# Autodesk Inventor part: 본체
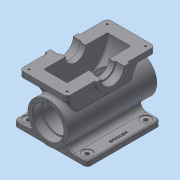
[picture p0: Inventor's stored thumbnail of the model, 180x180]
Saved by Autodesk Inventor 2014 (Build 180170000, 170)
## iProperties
Created: 2023-07
Part Number: 본체
Material: 일반
Document SubType Name: Modeling
Designer: dg
Density: 1 g/cm^3
Appearance: 기본값
Author: dg
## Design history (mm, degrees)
sketch "스케치1"
  geometry: L1 (-121, 0)-(121, 0); L2 (-121, 0)-(-121, 55); L3 (-121, 55)-(121, 55); L4 (121, 55)-(121, 0); L5 (-121, 42.5)-(-96, 42.5); L6 (-96, 42.5)-(-96, 38.5); L7 (-96, 38.5)-(96, 38.5); L8 (96, 38.5)-(96, 42.5); L9 (96, 42.5)-(121, 42.5); 2 further points
  constraints: 18 end point, 5 perpendicular, 3 parallel, 2 coincident, 2 point on line, 1 horizontal, 1 midpoint
  dimensions: "d0" = 242 distance of L1.start L1.end; "d1" = 110 diameter of L3 L1; "d2" = 85 diameter of L5 L1; "d3" = 77 diameter of L7 L1; "d4" = 85 diameter of L9 L1; "d5" = 25 distance between parallel lines of L4 L8; "d6" = 25 distance between parallel lines of L2 L6
revolve "회전1" sketch "스케치1" stored, may be unused: angle "d7" = 90 deg
node "작업 평면1"
sketch "스케치2"
  geometry: L1 (-100, -45)-(100, -45); L2 (100, -45)-(100, -60); L3 (100, -60)-(-100, -60); L4 (-100, -60)-(-100, -45); 2 further points
  constraints: 8 end point, 2 parallel, 1 horizontal, 1 midpoint, 1 perpendicular, 1 vertical alignment
  dimensions: "d9" = 60 distance from line of L3 point (0, 0); "d10" = 15 distance between parallel lines of L3 L1; "d11" = 200 distance between parallel lines of L2 L4
extrude "돌출1" join sketch "스케치2" stored distance "d12" = 200; taper "d13" = 0 deg
fillet "모깎기1" dims "d14" = 15
sketch "스케치3"
  geometry: L1 (-114, -60)-(86, -60) reference; L2 (-121, -55)-(-121, 55) reference; L3 (-114, 100)-(86, 100); L4 (86, -55)-(86, -60) reference; L5 (86, -60)-(-114, -60) reference; L6 (-114, -60)-(-114, -55) reference; L7 (-114, -55)-(-121, -55) reference; L8 (-121, -55)-(-121, -42.5) reference; L9 (-121, -42.5)-(-96, -42.5) reference; L10 (-96, -42.5)-(-96, -38.5) reference; L11 (-96, -38.5)-(96, -38.5) reference; L12 (96, -38.5)-(96, -42.5) reference; L13 (96, -42.5)-(121, -42.5) reference; L14 (121, -42.5)-(121, -55) reference; L15 (121, -55)-(86, -55) reference; L16 (-121, 55)-(121, 55) reference; L17 (121, 55)-(121, 42.5) reference; L18 (121, 42.5)-(96, 42.5) reference; L19 (96, 42.5)-(96, 38.5) reference; L20 (96, 38.5)-(-96, 38.5) reference; L21 (-96, 38.5)-(-96, 42.5) reference; L22 (-96, 42.5)-(-121, 42.5) reference; L23 (-121, 42.5)-(-121, 55) reference; A1 r 100 centre (-14, 100) between (-114, 100) and (86, 100); 2 further points
  constraints: 2 end point, 2 point on circle, 1 centre point, 1 coincident, 1 midpoint, 1 perpendicular
  dimensions: "d15" = 200 diameter of A1; "d16" = 160 distance from line of L1 A1.centre; "d17" = 107 distance from line of L2 A1.centre
extrude "돌출2" join sketch "스케치3" stored distance "d18" = 90; taper "d19" = 0 deg
sketch "스케치4"
  geometry: L1 (90, 200)-(90, 0) reference; L2 (0, 200)-(90, 200) reference; L3 (-20, 220)-(110, 220); L4 (110, 220)-(110, -20); L5 (110, -20)-(-20, -20); L6 (-20, -20)-(-20, 220); 5 further points
  constraints: 8 end point, 4 midpoint, 2 parallel, 1 horizontal, 1 horizontal alignment, 1 perpendicular, 1 vertical alignment
  dimensions: "d20" = 130 distance between parallel lines of L4 L6; "d21" = 240 distance between parallel lines of L5 L3
extrude "돌출3" join sketch "스케치4" distance "d22" = 15; taper "d23" = 0 deg
sketch "스케치5"
  geometry: L1 (-92.853, 38.5)-(-96, 38.5) reference; L2 (-96, 38.5)-(-96, 42.5) reference; L3 (-96, 42.5)-(-121, 42.5) reference; L4 (-121, 42.5)-(-121, 55) reference; L5 (-121, 55)-(-103.303, 55) reference; L6 (-112.869, 85)-(-134, 85) reference; L7 (-134, 85)-(-134, 100) reference; L8 (-134, 100)-(106, 100) reference; L9 (106, 100)-(106, 85) reference; L10 (106, 85)-(84.869, 85) reference; L11 (75.303, 55)-(121, 55) reference; L12 (121, 55)-(121, 42.5) reference; L13 (121, 42.5)-(96, 42.5) reference; L14 (96, 42.5)-(96, 38.5) reference; L15 (96, 38.5)-(64.853, 38.5) reference; L16 (86, -55)-(86, -60) reference; L17 (86, -60)-(-114, -60) reference; L18 (-114, -60)-(-114, -55) reference; L19 (-114, -55)-(-121, -55) reference; L20 (-121, -55)-(-121, -42.5) reference; L21 (-121, -42.5)-(-96, -42.5) reference; L22 (-96, -42.5)-(-96, -38.5) reference; L23 (-96, -38.5)-(96, -38.5) reference; L24 (96, -38.5)-(96, -42.5) reference; L25 (96, -42.5)-(121, -42.5) reference; L26 (121, -42.5)-(121, -55) reference; L27 (121, -55)-(86, -55) reference; C1 r 87 at (-14, 100); A1 r 100 centre (-14, 100) between (-92.853, 38.5) and (64.853, 38.5) reference; A2 r 100 centre (-14, 100) between (-112.869, 85) and (-103.303, 55) reference; A3 r 100 centre (-14, 100) between (75.303, 55) and (84.869, 85) reference; 1 further point
  constraints: 1 centre point, 1 coincident
  dimensions: "d24" = 87 radius of C1
  node "절단 모서리 투영2"
extrude "돌출4" cut sketch "스케치5" stored distance "d25" = 64; taper "d26" = 0 deg
sketch "스케치6"
  geometry: C1 r 38.5 at (0, 0) reference; C2 r 38.5 at (0, 0)
  constraints: 1 centre point, 1 coincident, 1 concentric
extrude "돌출5" cut sketch "스케치6" stored distance "d27" = 64; taper "d28" = 0 deg
sketch "스케치7"
  geometry: L1 (106, 85)-(84.869, 85) reference; L2 (75.303, 55)-(121, 55) reference; L3 (121, 55)-(121, 42.5) reference; L4 (121, 42.5)-(96, 42.5) reference; L5 (96, 42.5)-(96, 38.5) reference; L6 (96, 38.5)-(47.537, 38.5) reference; L7 (73, 100)-(106, 100) reference; L8 (106, 100)-(106, 85) reference; L9 (-112.869, 85)-(-134, 85) reference; L10 (-134, 85)-(-134, 100) reference; L11 (-134, 100)-(-101, 100) reference; L12 (-75.537, 38.5)-(-96, 38.5) reference; L13 (-96, 38.5)-(-96, 42.5) reference; L14 (-96, 42.5)-(-121, 42.5) reference; L15 (-121, 42.5)-(-121, 55) reference; L16 (-121, 55)-(-103.303, 55) reference; L17 (86, -55)-(86, -60) reference; L18 (86, -60)-(-114, -60) reference; L19 (-114, -60)-(-114, -55) reference; L20 (-114, -55)-(-121, -55) reference; L21 (-121, -55)-(-121, -42.5) reference; L22 (-121, -42.5)-(-96, -42.5) reference; L23 (-96, -42.5)-(-96, -38.5) reference; L24 (-96, -38.5)-(96, -38.5) reference; L25 (96, -38.5)-(96, -42.5) reference; L26 (96, -42.5)-(121, -42.5) reference; L27 (121, -42.5)-(121, -55) reference; L28 (121, -55)-(86, -55) reference; L29 (-101, 100)-(73, 100) reference; L30 (-59, 100)-(31, 100); A1 r 100 centre (-14, 100) between (75.303, 55) and (84.869, 85) reference; A2 r 87 centre (-14, 100) between (47.537, 38.5) and (73, 100) reference; A3 r 87 centre (-14, 100) between (-101, 100) and (-75.537, 38.5) reference; A4 r 100 centre (-14, 100) between (-112.869, 85) and (-103.303, 55) reference; A5 r 45 centre (-14, 100) between (-59, 100) and (31, 100); 3 further points
  constraints: 3 coincident, 2 end point, 2 midpoint, 2 point on circle, 1 centre point, 1 collinear
  dimensions: "d29" = 90 diameter of A5
extrude "돌출6" join sketch "스케치7" stored distance "d30" = 140; taper "d31" = 0 deg
extrude "돌출7" cut sketch "스케치5" stored distance "d32" = 64; taper "d33" = 0 deg
hole "구멍1" diameter "d36" = 55; stored, may be unused: countersink angle "d40" = 90 deg, drill point angle "d42" = 118 deg; dims "d34" = 10, "d35" = 10, "d37" = 6, "d38" = 62, "d39" = 23, "d41" = 65.75
fillet "모깎기2" dims "d43" = 10
sketch "스케치8"
  geometry: L1 (-15, 56)-(-38, 56) reference; L2 (-38, 132)-(-33, 132) reference; L3 (-33, 132)-(-33, 197) reference; L4 (-23, 207)-(87, 207) reference; L5 (97, 197)-(97, 132) reference; L6 (97, 132)-(102, 132) reference; L7 (102, 132)-(102, 118) reference; L8 (102, 118)-(79, 118) reference; L9 (79, 118)-(79, 114.5) reference; L10 (79, 114.5)-(64, 114.5) reference; L11 (64, 114.5)-(64, 174) reference; L12 (64, 174)-(0, 174) reference; L13 (0, 174)-(0, 114.5) reference; L14 (0, 114.5)-(-15, 114.5) reference; L15 (-15, 114.5)-(-15, 118) reference; L16 (-15, 118)-(-38, 118) reference; L17 (-38, 118)-(-38, 132) reference; L18 (102, 42)-(97, 42) reference; L19 (97, 42)-(97, -23) reference; L20 (87, -33)-(-23, -33) reference; L21 (-33, -23)-(-33, 42) reference; L22 (-33, 42)-(-38, 42) reference; L23 (-38, 42)-(-38, 56) reference; L24 (-38, 56)-(-15, 56) reference; L25 (-15, 56)-(-15, 59.5) reference; L26 (-15, 59.5)-(0, 59.5) reference; L27 (0, 59.5)-(0, 0) reference; L28 (0, 0)-(64, 0) reference; L29 (64, 0)-(64, 59.5) reference; L30 (64, 59.5)-(79, 59.5) reference; L31 (79, 59.5)-(79, 56) reference; L32 (79, 56)-(102, 56) reference; L33 (102, 56)-(102, 42) reference; L34 (-15, 59.5)-(-15, 114.5) reference; A1 r 10 centre (-23, 197) between (-23, 207) and (-33, 197) reference; A2 r 10 centre (87, 197) between (97, 197) and (87, 207) reference; A3 r 10 centre (87, -23) between (87, -33) and (97, -23) reference; A4 r 10 centre (-23, -23) between (-33, -23) and (-23, -33) reference; 4 further points
  constraints: 1 coincident, 1 midpoint
  dimensions: "d44" = 52 horizontal distance of point (32, 101) point (-20, -20); "d46" = 31 distance from line of point (-15, 87) L1; "d47" = 107 vertical distance of point (-20, -20) point (-15, 87)
hole "구멍2" sketch "스케치8" at (-20, -20) diameter "d48" = 4.917; stored, may be unused: countersink angle "d52" = 90 deg, drill point angle "d54" = 118 deg; dims "d49" = 30, "d50" = 4, "d51" = 2, "d53" = 32.5
node "작업 평면2"
sketch "스케치9" dims "d56" = 74
  geometry: L1 (-100, -14)-(-55, -14); L2 (-100, -14)-(-68.18, -45.82); A1 r 45 centre (-100, -14) between (-100, -59) and (-100, 31) reference; 3 further points
  constraints: 4 end point, 2 point on circle, 1 coincident, 1 point on line, 3 other
  dimensions: "d55" = 45 deg angle of L1 L2
hole "구멍3" sketch "스케치9" at (-73.837, -40.163) diameter "d57" = 4.134; stored, may be unused: countersink angle "d61" = 90 deg, drill point angle "d63" = 118 deg; dims "d58" = 10, "d59" = 4, "d60" = 2, "d62" = 12
sketch "스케치10"
  geometry: C1 r 55 at (0, 0) reference; 1 further point
  constraints: 1 vertical alignment
  dimensions: "d64" = 48.5 distance of C1.centre point (0, 48.5)
hole "구멍4" sketch "스케치10" at (0, 48.5) diameter "d65" = 4.134; stored, may be unused: countersink angle "d69" = 90 deg, drill point angle "d71" = 118 deg; dims "d66" = 10, "d67" = 4, "d68" = 2, "d70" = 12
node "작업 평면3"
fillet "모깎기3" dims "d75" = 10
sketch "스케치11"
  geometry: L1 (-26.754, 200)-(0, 200) reference; L2 (-36.754, 190)-(-36.754, 10) reference; L3 (31.623, 0)-(0, 0) reference; L4 (0, 0)-(-26.754, 0) reference; L5 (-36.754, 10)-(-36.754, 190) reference; L6 (-26.754, 200)-(0, 200) reference; L7 (0, 0)-(0, 200) reference; L8 (31.623, -7)-(31.623, 0) reference; L9 (94.868, -7)-(31.623, -7) reference; L10 (94.868, 0)-(94.868, -7) reference; L11 (126.491, 0)-(94.868, 0) reference; L12 (126.491, 200)-(126.491, 0) reference; L13 (94.868, 200)-(126.491, 200) reference; L14 (94.868, 235)-(94.868, 200) reference; L15 (31.623, 235)-(94.868, 235) reference; L16 (31.623, 200)-(31.623, 235) reference; L17 (0, 200)-(31.623, 200) reference; L18 (153.246, 0)-(126.491, 0) reference; L19 (163.246, 190)-(163.246, 10) reference; L20 (126.491, 200)-(153.246, 200) reference; A1 r 10 centre (-26.754, 10) between (-36.754, 10) and (-26.754, 0) reference; A2 r 10 centre (-26.754, 190) between (-26.754, 200) and (-36.754, 190) reference; A3 r 10 centre (153.246, 10) between (153.246, 0) and (163.246, 10) reference; A4 r 10 centre (153.246, 190) between (163.246, 190) and (153.246, 200) reference; 3 further points
  constraints: 1 midpoint
  dimensions: "d76" = 100 distance from line of L1 point (-36.754, 100); "d77" = 80 vertical distance of point (-36.754, 100) point (-16.754, 180); "d78" = 80 horizontal distance of point (-16.754, 180) point (63.246, 114)
hole "구멍5" sketch "스케치11" at (-16.754, 180) diameter "d79" = 11; stored, may be unused: countersink angle "d83" = 90 deg, drill point angle "d85" = 118 deg; dims "d80" = 10, "d81" = 28, "d82" = 2, "d84" = 19.25
node "작업 평면4"
fillet "모깎기4" dims "d86" = 1.1
fillet "모깎기5" dims "d87" = 3
fillet "모깎기6" dims "d88" = 3
fillet "모깎기7" dims "d89" = 3
fillet "모깎기8" dims "d90" = 3
chamfer "모따기1" distance "d91" = 1; stored, may be unused: second distance "d92" = 2, angle "d93" = 45 deg
chamfer "모따기2" distance "d94" = 1; stored, may be unused: second distance "d95" = 2, angle "d96" = 45 deg
fillet "모깎기9" dims "d97" = 1
fillet "모깎기10" dims "d98" = 3
fillet "모깎기11" dims "d99" = 3
fillet "모깎기12" dims "d100" = 3
fillet "모깎기13" dims "d101" = 3
sketch "스케치12"
  geometry: L1 (5.754, -66)-(5.754, -128) reference; L2 (36.754, -187)-(36.754, -7) reference; 3 further points
  constraints: 1 horizontal alignment, 1 midpoint, 1 other
  dimensions: "d102" = 15 distance from line of L2 point (21.754, -97)
feature "엠보싱1" sketch "스케치12" dims "d9" = 60, "d10" = 15, "d11" = 200, "d103" = 0.5, "d104" = 0
node "솔리드1"
mirror "대칭1"
mirror "대칭2"
mirror "대칭3"
mirror "대칭4"
mirror "대칭5"
pattern_circular "원형 패턴1" dims angle "d73" = 360 deg
mirror "대칭6"
mirror "대칭7"
mirror "대칭8"
node "절단 모서리 투영1"
node "절단 모서리 투영3"
node "절단 모서리 투영4"
node "절단 모서리 투영5"
other parameters: "d8" = -107
